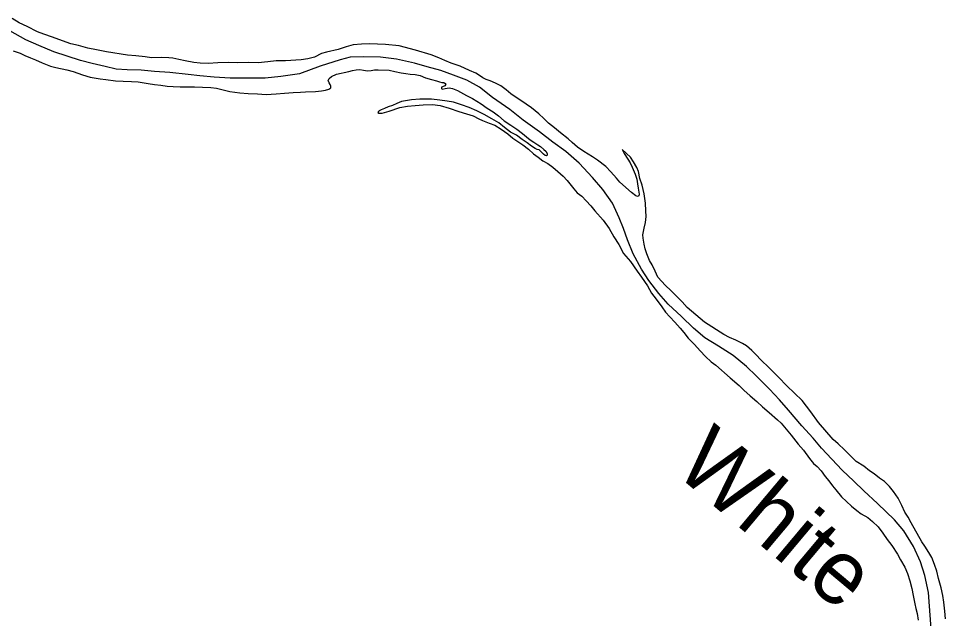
# Model space of a CAD drawing. Extents: x 1377389 to 1380723, y 1168351 to 1170484.
# Drawn here: x 1377867 to 1377943, y 1169789.7 to 1169838.9 of the extents above; entities that cross this region are included whole.
import ezdxf

# ---------------------------------------------------------------- set-up
doc = ezdxf.new("R2010")
doc.units = 0
doc.layers.add('B_Fill', color=7, linetype='Continuous')

msp = doc.modelspace()

# ---------------------------------------------------------------- linework, layer by layer
at = {"layer": 'B_Fill'}
for points in [[(1377901.437, 1169835.626), (1377900.799, 1169835.886), (1377899.515, 1169836.276), (1377898.184, 1169836.615), (1377897.069, 1169836.73), (1377896.408, 1169836.749), (1377895.786, 1169836.789), (1377895.087, 1169836.757), (1377894.408, 1169836.695), (1377893.852, 1169836.537), (1377893.169, 1169836.314), (1377892.225, 1169836.094), (1377891.828, 1169835.981), (1377891.246, 1169835.701), (1377890.7, 1169835.563), (1377890.142, 1169835.475), (1377888.874, 1169835.405), (1377888.103, 1169835.39), (1377887.415, 1169835.318), (1377886.627, 1169835.233), (1377885.815, 1169835.267), (1377884.966, 1169835.22), (1377884.194, 1169835.255), (1377883.305, 1169835.217), (1377882.515, 1169835.182), (1377881.854, 1169835.191), (1377881.352, 1169835.265), (1377880.637, 1169835.392), (1377880.113, 1169835.506), (1377879.62, 1169835.6), (1377879.298, 1169835.65), (1377878.687, 1169835.661), (1377877.877, 1169835.645), (1377877.354, 1169835.709), (1377876.591, 1169835.805), (1377875.918, 1169835.863), (1377874.198, 1169836.139), (1377873.363, 1169836.293), (1377872.647, 1169836.441), (1377871.901, 1169836.637), (1377871.265, 1169836.788), (1377870.577, 1169837.026), (1377869.757, 1169837.331), (1377869.048, 1169837.589), (1377868.522, 1169837.783), (1377867.688, 1169838.218), (1377867.038, 1169838.518), (1377866.457, 1169838.86)], [(1377901.437, 1169835.626), (1377900.799, 1169835.886), (1377899.515, 1169836.276), (1377898.184, 1169836.615), (1377897.069, 1169836.73), (1377896.408, 1169836.749), (1377895.786, 1169836.789), (1377895.087, 1169836.757), (1377894.408, 1169836.695), (1377893.852, 1169836.537), (1377893.169, 1169836.314), (1377892.225, 1169836.094), (1377891.828, 1169835.981), (1377891.246, 1169835.701), (1377890.7, 1169835.563), (1377890.142, 1169835.475), (1377888.874, 1169835.405), (1377888.103, 1169835.39), (1377887.415, 1169835.318), (1377886.627, 1169835.233), (1377885.815, 1169835.267), (1377884.966, 1169835.22), (1377884.194, 1169835.255), (1377883.305, 1169835.217), (1377882.515, 1169835.182), (1377881.854, 1169835.191), (1377881.352, 1169835.265), (1377880.637, 1169835.392), (1377880.113, 1169835.506), (1377879.62, 1169835.6), (1377879.298, 1169835.65), (1377878.687, 1169835.661), (1377877.877, 1169835.645), (1377877.354, 1169835.709), (1377876.591, 1169835.805), (1377875.918, 1169835.863), (1377874.198, 1169836.139), (1377873.363, 1169836.293), (1377872.647, 1169836.441), (1377871.901, 1169836.637), (1377871.265, 1169836.788), (1377870.577, 1169837.026), (1377869.757, 1169837.331), (1377869.048, 1169837.589), (1377868.522, 1169837.783), (1377867.688, 1169838.218), (1377867.038, 1169838.518), (1377866.457, 1169838.86)], [(1377919.466, 1169816.315), (1377918.653, 1169817.372), (1377918.053, 1169818.306), (1377917.383, 1169819.568), (1377916.917, 1169820.717), (1377916.567, 1169821.648), (1377916.229, 1169822.53), (1377915.671, 1169823.725), (1377914.886, 1169824.844), (1377914.044, 1169825.84), (1377912.947, 1169826.998), (1377911.846, 1169827.946), (1377910.791, 1169828.724), (1377909.704, 1169829.572), (1377908.353, 1169830.522), (1377907.255, 1169831.389), (1377905.832, 1169832.397), (1377904.785, 1169833.236), (1377903.736, 1169833.814), (1377902.653, 1169834.21), (1377901.6, 1169834.598), (1377900.469, 1169834.913), (1377899.449, 1169835.201), (1377897.957, 1169835.525), (1377896.651, 1169835.693), (1377895.259, 1169835.729), (1377894.169, 1169835.684), (1377893.335, 1169835.477), (1377891.71, 1169834.944), (1377890.008, 1169834.338), (1377888.484, 1169834.099), (1377887.187, 1169833.967), (1377885.786, 1169833.962), (1377884.315, 1169833.965), (1377883.021, 1169834.044), (1377881.836, 1169834.167), (1377880.872, 1169834.267), (1377879.366, 1169834.429), (1377878.132, 1169834.51), (1377877.038, 1169834.625), (1377875.876, 1169834.649), (1377874.984, 1169834.71), (1377874.076, 1169834.922), (1377873.018, 1169835.169), (1377872.049, 1169835.419), (1377869.865, 1169836.121), (1377868.647, 1169836.654), (1377867.582, 1169837.121), (1377866.248, 1169837.861)], [(1377866.519, 1169836.225), (1377867.096, 1169836.013), (1377867.502, 1169835.825), (1377867.959, 1169835.629), (1377868.354, 1169835.471), (1377868.922, 1169835.239), (1377869.591, 1169834.959), (1377870.026, 1169834.833), (1377870.942, 1169834.641), (1377871.457, 1169834.507), (1377872.206, 1169834.24), (1377872.853, 1169834.04), (1377873.657, 1169833.916), (1377874.129, 1169833.861), (1377874.913, 1169833.755), (1377875.555, 1169833.736), (1377876.226, 1169833.697), (1377876.778, 1169833.664), (1377877.592, 1169833.54), (1377878.116, 1169833.446), (1377878.648, 1169833.403), (1377879.15, 1169833.329), (1377879.662, 1169833.275), (1377880.214, 1169833.253), (1377880.884, 1169833.254), (1377881.395, 1169833.25), (1377882.056, 1169833.231), (1377882.747, 1169833.213), (1377883.2, 1169833.138), (1377884.309, 1169832.882)], [(1377866.519, 1169836.225), (1377867.096, 1169836.013), (1377867.502, 1169835.825), (1377867.959, 1169835.629), (1377868.354, 1169835.471), (1377868.922, 1169835.239), (1377869.591, 1169834.959), (1377870.026, 1169834.833), (1377870.942, 1169834.641), (1377871.457, 1169834.507), (1377872.206, 1169834.24), (1377872.853, 1169834.04), (1377873.657, 1169833.916), (1377874.129, 1169833.861), (1377874.913, 1169833.755), (1377875.555, 1169833.736), (1377876.226, 1169833.697), (1377876.778, 1169833.664), (1377877.592, 1169833.54), (1377878.116, 1169833.446), (1377878.648, 1169833.403), (1377879.15, 1169833.329), (1377879.662, 1169833.275), (1377880.214, 1169833.253), (1377880.884, 1169833.254), (1377881.395, 1169833.25), (1377882.056, 1169833.231), (1377882.747, 1169833.213), (1377883.2, 1169833.138), (1377884.309, 1169832.882)], [(1377937.974, 1169800.901), (1377937.585, 1169801.18), (1377937.124, 1169801.536), (1377936.756, 1169801.785), (1377936.284, 1169802.151), (1377935.671, 1169802.533), (1377935.217, 1169802.979), (1377934.701, 1169803.484), (1377934.194, 1169803.99), (1377933.763, 1169804.357), (1377932.568, 1169805.743), (1377931.941, 1169806.605), (1377931.231, 1169807.535), (1377929.982, 1169808.749), (1377929.28, 1169809.449), (1377928.535, 1169810.207), (1377927.854, 1169810.867), (1377927.46, 1169811.296), (1377927.099, 1169811.635), (1377926.677, 1169812.013), (1377926.34, 1169812.223), (1377925.792, 1169812.486), (1377925.274, 1169812.72), (1377924.796, 1169812.966), (1377923.223, 1169813.978), (1377922.523, 1169814.578), (1377921.804, 1169815.177), (1377921.38, 1169815.624), (1377920.904, 1169816.121), (1377920.481, 1169816.528), (1377920.005, 1169817.004), (1377919.716, 1169817.286), (1377919.405, 1169817.647), (1377919.169, 1169818.141), (1377918.933, 1169818.655), (1377918.701, 1169819.029), (1377918.484, 1169819.573), (1377918.361, 1169819.981), (1377918.269, 1169820.359), (1377918.194, 1169820.848), (1377918.175, 1169821.118), (1377918.268, 1169821.672), (1377918.373, 1169822.147), (1377918.428, 1169822.63), (1377918.414, 1169823.091), (1377918.374, 1169823.722), (1377918.28, 1169824.481), (1377918.108, 1169825.197), (1377917.93, 1169825.753), (1377917.802, 1169826.321), (1377917.661, 1169826.657), (1377917.407, 1169827.11), (1377917.155, 1169827.483), (1377916.465, 1169828.123), (1377916.645, 1169827.798), (1377916.93, 1169827.336), (1377917.13, 1169827.021), (1377917.301, 1169826.676), (1377917.529, 1169826.101), (1377917.672, 1169825.695), (1377917.734, 1169825.316), (1377917.785, 1169824.956), (1377917.835, 1169824.637), (1377917.86, 1169824.467), (1377917.824, 1169824.336), (1377917.736, 1169824.273), (1377917.605, 1169824.319), (1377917.246, 1169824.598), (1377916.268, 1169825.449), (1377916.007, 1169825.782), (1377915.551, 1169826.289), (1377915.137, 1169826.727), (1377914.46, 1169827.247), (1377914.041, 1169827.534), (1377913.337, 1169827.953), (1377912.815, 1169828.318), (1377912.364, 1169828.684), (1377912.044, 1169828.985), (1377911.408, 1169829.486), (1377910.935, 1169829.892), (1377910.442, 1169830.288), (1377910.05, 1169830.656), (1377909.628, 1169831.044), (1377909.032, 1169831.536), (1377908.612, 1169831.834), (1377908.152, 1169832.14), (1377907.702, 1169832.436), (1377907.354, 1169832.696), (1377906.954, 1169833.014), (1377906.523, 1169833.341), (1377906.086, 1169833.568), (1377905.64, 1169833.744), (1377905.326, 1169833.865), (1377905.051, 1169833.996), (1377904.785, 1169834.188), (1377904.469, 1169834.369), (1377903.962, 1169834.593), (1377903.18, 1169834.949), (1377902.451, 1169835.207), (1377901.924, 1169835.431), (1377901.437, 1169835.626)], [(1377937.974, 1169800.901), (1377937.585, 1169801.18), (1377937.124, 1169801.536), (1377936.756, 1169801.785), (1377936.284, 1169802.151), (1377935.671, 1169802.533), (1377935.217, 1169802.979), (1377934.701, 1169803.484), (1377934.194, 1169803.99), (1377933.763, 1169804.357), (1377932.568, 1169805.743), (1377931.941, 1169806.605), (1377931.231, 1169807.535), (1377929.982, 1169808.749), (1377929.28, 1169809.449), (1377928.535, 1169810.207), (1377927.854, 1169810.867), (1377927.46, 1169811.296), (1377927.099, 1169811.635), (1377926.677, 1169812.013), (1377926.34, 1169812.223), (1377925.792, 1169812.486), (1377925.274, 1169812.72), (1377924.796, 1169812.966), (1377923.223, 1169813.978), (1377922.523, 1169814.578), (1377921.804, 1169815.177), (1377921.38, 1169815.624), (1377920.904, 1169816.121), (1377920.481, 1169816.528), (1377920.005, 1169817.004), (1377919.716, 1169817.286), (1377919.405, 1169817.647), (1377919.169, 1169818.141), (1377918.933, 1169818.655), (1377918.701, 1169819.029), (1377918.484, 1169819.573), (1377918.361, 1169819.981), (1377918.269, 1169820.359), (1377918.194, 1169820.848), (1377918.175, 1169821.118), (1377918.268, 1169821.672), (1377918.373, 1169822.147), (1377918.428, 1169822.63), (1377918.414, 1169823.091), (1377918.374, 1169823.722), (1377918.28, 1169824.481), (1377918.108, 1169825.197), (1377917.93, 1169825.753), (1377917.802, 1169826.321), (1377917.661, 1169826.657), (1377917.407, 1169827.11), (1377917.155, 1169827.483), (1377916.465, 1169828.123), (1377916.645, 1169827.798), (1377916.93, 1169827.336), (1377917.13, 1169827.021), (1377917.301, 1169826.676), (1377917.529, 1169826.101), (1377917.672, 1169825.695), (1377917.734, 1169825.316), (1377917.785, 1169824.956), (1377917.835, 1169824.637), (1377917.86, 1169824.467), (1377917.824, 1169824.336), (1377917.736, 1169824.273), (1377917.605, 1169824.319), (1377917.246, 1169824.598), (1377916.268, 1169825.449), (1377916.007, 1169825.782), (1377915.551, 1169826.289), (1377915.137, 1169826.727), (1377914.46, 1169827.247), (1377914.041, 1169827.534), (1377913.337, 1169827.953), (1377912.815, 1169828.318), (1377912.364, 1169828.684), (1377912.044, 1169828.985), (1377911.408, 1169829.486), (1377910.935, 1169829.892), (1377910.442, 1169830.288), (1377910.05, 1169830.656), (1377909.628, 1169831.044), (1377909.032, 1169831.536), (1377908.612, 1169831.834), (1377908.152, 1169832.14), (1377907.702, 1169832.436), (1377907.354, 1169832.696), (1377906.954, 1169833.014), (1377906.523, 1169833.341), (1377906.086, 1169833.568), (1377905.64, 1169833.744), (1377905.326, 1169833.865), (1377905.051, 1169833.996), (1377904.785, 1169834.188), (1377904.469, 1169834.369), (1377903.962, 1169834.593), (1377903.18, 1169834.949), (1377902.451, 1169835.207), (1377901.924, 1169835.431), (1377901.437, 1169835.626)], [(1377884.309, 1169832.882), (1377885.113, 1169832.757), (1377885.815, 1169832.72), (1377886.577, 1169832.674), (1377887.279, 1169832.626), (1377888.098, 1169832.682), (1377888.786, 1169832.754), (1377889.485, 1169832.807), (1377890.085, 1169832.836), (1377890.505, 1169832.85), (1377891.315, 1169832.865), (1377891.803, 1169832.931), (1377892.152, 1169832.992), (1377892.41, 1169833.061), (1377892.586, 1169833.177), (1377892.582, 1169833.327), (1377892.528, 1169833.456), (1377892.454, 1169833.584), (1377892.367, 1169833.782), (1377892.452, 1169833.945), (1377892.648, 1169834.101), (1377893.042, 1169834.294), (1377894.055, 1169834.527), (1377894.363, 1169834.597), (1377894.672, 1169834.657), (1377894.951, 1169834.686), (1377895.263, 1169834.626), (1377895.595, 1169834.577), (1377895.875, 1169834.596), (1377896.153, 1169834.665), (1377896.473, 1169834.665), (1377897.355, 1169834.623), (1377897.829, 1169834.508), (1377898.353, 1169834.404), (1377898.725, 1169834.356), (1377899.087, 1169834.297), (1377899.488, 1169834.28), (1377899.901, 1169834.183), (1377900.347, 1169834.006), (1377900.832, 1169833.861), (1377901.246, 1169833.744), (1377901.488, 1169833.672), (1377901.69, 1169833.628), (1377901.851, 1169833.603), (1377901.963, 1169833.547), (1377902.006, 1169833.448), (1377901.929, 1169833.355), (1377901.731, 1169833.268), (1377901.653, 1169833.226), (1377901.646, 1169833.125), (1377901.708, 1169833.067), (1377901.946, 1169833.115), (1377902.295, 1169833.176), (1377902.556, 1169833.134), (1377902.962, 1169832.967), (1377903.696, 1169832.539), (1377904.193, 1169832.314), (1377904.918, 1169831.866), (1377905.399, 1169831.52), (1377905.889, 1169831.215), (1377906.32, 1169830.878), (1377906.803, 1169830.482), (1377907.334, 1169830.128), (1377907.825, 1169829.793), (1377908.297, 1169829.437), (1377908.615, 1169829.166), (1377908.923, 1169828.925), (1377909.22, 1169828.714), (1377909.557, 1169828.504), (1377909.772, 1169828.361), (1377910.059, 1169828.129), (1377910.204, 1169827.983), (1377910.31, 1169827.786), (1377910.324, 1169827.646), (1377910.276, 1169827.605), (1377910.165, 1169827.631), (1377910.021, 1169827.737), (1377909.928, 1169827.834), (1377909.815, 1169827.941), (1377909.67, 1169828.097), (1377909.488, 1169828.131), (1377909.326, 1169828.196), (1377909.029, 1169828.407), (1377908.691, 1169828.667), (1377908.262, 1169828.944), (1377907.811, 1169829.291), (1377907.302, 1169829.555), (1377906.83, 1169829.921), (1377906.348, 1169830.297), (1377905.787, 1169830.65), (1377905.165, 1169830.991), (1377904.545, 1169831.303), (1377903.916, 1169831.563), (1377903.309, 1169831.784), (1377902.642, 1169831.994), (1377902.119, 1169832.087), (1377901.525, 1169832.179), (1377900.832, 1169832.247), (1377899.882, 1169832.237), (1377899.193, 1169832.194), (1377898.386, 1169832.068)], [(1377884.309, 1169832.882), (1377885.113, 1169832.757), (1377885.815, 1169832.72), (1377886.577, 1169832.674), (1377887.279, 1169832.626), (1377888.098, 1169832.682), (1377888.786, 1169832.754), (1377889.485, 1169832.807), (1377890.085, 1169832.836), (1377890.505, 1169832.85), (1377891.315, 1169832.865), (1377891.803, 1169832.931), (1377892.152, 1169832.992), (1377892.41, 1169833.061), (1377892.586, 1169833.177), (1377892.582, 1169833.327), (1377892.528, 1169833.456), (1377892.454, 1169833.584), (1377892.367, 1169833.782), (1377892.452, 1169833.945), (1377892.648, 1169834.101), (1377893.042, 1169834.294), (1377894.055, 1169834.527), (1377894.363, 1169834.597), (1377894.672, 1169834.657), (1377894.951, 1169834.686), (1377895.263, 1169834.626), (1377895.595, 1169834.577), (1377895.875, 1169834.596), (1377896.153, 1169834.665), (1377896.473, 1169834.665), (1377897.355, 1169834.623), (1377897.829, 1169834.508), (1377898.353, 1169834.404), (1377898.725, 1169834.356), (1377899.087, 1169834.297), (1377899.488, 1169834.28), (1377899.901, 1169834.183), (1377900.347, 1169834.006), (1377900.832, 1169833.861), (1377901.246, 1169833.744), (1377901.488, 1169833.672), (1377901.69, 1169833.628), (1377901.851, 1169833.603), (1377901.963, 1169833.547), (1377902.006, 1169833.448), (1377901.929, 1169833.355), (1377901.731, 1169833.268), (1377901.653, 1169833.226), (1377901.646, 1169833.125), (1377901.708, 1169833.067), (1377901.946, 1169833.115), (1377902.295, 1169833.176), (1377902.556, 1169833.134), (1377902.962, 1169832.967), (1377903.696, 1169832.539), (1377904.193, 1169832.314), (1377904.918, 1169831.866), (1377905.399, 1169831.52), (1377905.889, 1169831.215), (1377906.32, 1169830.878), (1377906.803, 1169830.482), (1377907.334, 1169830.128), (1377907.825, 1169829.793), (1377908.297, 1169829.437), (1377908.615, 1169829.166), (1377908.923, 1169828.925), (1377909.22, 1169828.714), (1377909.557, 1169828.504), (1377909.772, 1169828.361), (1377910.059, 1169828.129), (1377910.204, 1169827.983), (1377910.31, 1169827.786), (1377910.324, 1169827.646), (1377910.276, 1169827.605), (1377910.165, 1169827.631), (1377910.021, 1169827.737), (1377909.928, 1169827.834), (1377909.815, 1169827.941), (1377909.67, 1169828.097), (1377909.488, 1169828.131), (1377909.326, 1169828.196), (1377909.029, 1169828.407), (1377908.691, 1169828.667), (1377908.262, 1169828.944), (1377907.811, 1169829.291), (1377907.302, 1169829.555), (1377906.83, 1169829.921), (1377906.348, 1169830.297), (1377905.787, 1169830.65), (1377905.165, 1169830.991), (1377904.545, 1169831.303), (1377903.916, 1169831.563), (1377903.309, 1169831.784), (1377902.642, 1169831.994), (1377902.119, 1169832.087), (1377901.525, 1169832.179), (1377900.832, 1169832.247), (1377899.882, 1169832.237), (1377899.193, 1169832.194), (1377898.386, 1169832.068)], [(1377898.386, 1169832.068), (1377897.991, 1169831.895), (1377897.646, 1169831.734), (1377897.279, 1169831.612), (1377896.973, 1169831.472), (1377896.707, 1169831.363), (1377896.549, 1169831.288), (1377896.481, 1169831.225), (1377896.443, 1169831.144), (1377896.515, 1169831.096), (1377896.785, 1169831.105), (1377897.36, 1169831.273), (1377898.252, 1169831.553), (1377898.869, 1169831.663), (1377899.497, 1169831.733), (1377900.156, 1169831.794), (1377900.906, 1169831.808), (1377901.539, 1169831.728), (1377902.287, 1169831.501), (1377903.076, 1169831.246), (1377903.712, 1169831.055), (1377904.258, 1169830.882), (1377904.706, 1169830.636), (1377905.02, 1169830.505), (1377905.568, 1169830.282), (1377906.034, 1169830.107), (1377906.554, 1169829.782), (1377907.097, 1169829.408), (1377907.498, 1169829.06), (1377907.835, 1169828.84), (1377908.316, 1169828.495), (1377908.778, 1169828.138), (1377909.21, 1169827.771), (1377909.578, 1169827.502), (1377909.958, 1169827.203), (1377910.366, 1169826.966), (1377910.785, 1169826.668), (1377911.187, 1169826.31), (1377911.629, 1169825.933), (1377911.971, 1169825.573), (1377912.502, 1169824.888), (1377912.792, 1169824.576), (1377913.151, 1169824.297), (1377913.524, 1169823.908), (1377913.907, 1169823.499), (1377914.24, 1169823.098), (1377914.905, 1169822.327), (1377915.406, 1169821.651), (1377915.778, 1169820.971), (1377916.208, 1169820.323), (1377916.591, 1169819.603), (1377917.142, 1169818.949), (1377917.688, 1169818.134), (1377918.053, 1169817.664), (1377918.556, 1169816.948), (1377918.865, 1169816.346), (1377919.271, 1169815.838), (1377919.711, 1169815.23), (1377920.015, 1169814.778), (1377920.377, 1169814.409), (1377920.791, 1169813.961), (1377921.217, 1169813.483), (1377921.538, 1169813.112), (1377921.893, 1169812.662), (1377922.41, 1169812.127), (1377922.866, 1169811.61), (1377923.301, 1169811.163), (1377923.765, 1169810.716), (1377924.164, 1169810.438), (1377925.328, 1169809.402), (1377926.058, 1169808.764), (1377926.46, 1169808.396), (1377926.955, 1169807.93), (1377927.5, 1169807.456), (1377927.974, 1169807.02), (1377928.529, 1169806.556), (1377929.198, 1169805.966), (1377929.508, 1169805.675), (1377929.913, 1169805.197), (1377930.329, 1169804.698), (1377930.893, 1169803.954), (1377931.329, 1169803.457), (1377931.83, 1169802.791), (1377932.163, 1169802.38), (1377932.461, 1169802.129), (1377932.782, 1169801.788), (1377933.128, 1169801.298), (1377933.408, 1169800.966), (1377933.721, 1169800.555), (1377933.982, 1169800.212), (1377934.451, 1169799.635), (1377934.853, 1169799.267), (1377935.275, 1169798.88), (1377935.717, 1169798.523), (1377936.075, 1169798.253), (1377936.605, 1169797.959), (1377937.006, 1169797.621), (1377937.45, 1169797.184), (1377937.836, 1169796.675), (1377938.203, 1169796.145), (1377938.589, 1169795.646)], [(1377898.386, 1169832.068), (1377897.991, 1169831.895), (1377897.646, 1169831.734), (1377897.279, 1169831.612), (1377896.973, 1169831.472), (1377896.707, 1169831.363), (1377896.549, 1169831.288), (1377896.481, 1169831.225), (1377896.443, 1169831.144), (1377896.515, 1169831.096), (1377896.785, 1169831.105), (1377897.36, 1169831.273), (1377898.252, 1169831.553), (1377898.869, 1169831.663), (1377899.497, 1169831.733), (1377900.156, 1169831.794), (1377900.906, 1169831.808), (1377901.539, 1169831.728), (1377902.287, 1169831.501), (1377903.076, 1169831.246), (1377903.712, 1169831.055), (1377904.258, 1169830.882), (1377904.706, 1169830.636), (1377905.02, 1169830.505), (1377905.568, 1169830.282), (1377906.034, 1169830.107), (1377906.554, 1169829.782), (1377907.097, 1169829.408), (1377907.498, 1169829.06), (1377907.835, 1169828.84), (1377908.316, 1169828.495), (1377908.778, 1169828.138), (1377909.21, 1169827.771), (1377909.578, 1169827.502), (1377909.958, 1169827.203), (1377910.366, 1169826.966), (1377910.785, 1169826.668), (1377911.187, 1169826.31), (1377911.629, 1169825.933), (1377911.971, 1169825.573), (1377912.502, 1169824.888), (1377912.792, 1169824.576), (1377913.151, 1169824.297), (1377913.524, 1169823.908), (1377913.907, 1169823.499), (1377914.24, 1169823.098), (1377914.905, 1169822.327), (1377915.406, 1169821.651), (1377915.778, 1169820.971), (1377916.208, 1169820.323), (1377916.591, 1169819.603), (1377917.142, 1169818.949), (1377917.688, 1169818.134), (1377918.053, 1169817.664), (1377918.556, 1169816.948), (1377918.865, 1169816.346), (1377919.271, 1169815.838), (1377919.711, 1169815.23), (1377920.015, 1169814.778), (1377920.377, 1169814.409), (1377920.791, 1169813.961), (1377921.217, 1169813.483), (1377921.538, 1169813.112), (1377921.893, 1169812.662), (1377922.41, 1169812.127), (1377922.866, 1169811.61), (1377923.301, 1169811.163), (1377923.765, 1169810.716), (1377924.164, 1169810.438), (1377925.328, 1169809.402), (1377926.058, 1169808.764), (1377926.46, 1169808.396), (1377926.955, 1169807.93), (1377927.5, 1169807.456), (1377927.974, 1169807.02), (1377928.529, 1169806.556), (1377929.198, 1169805.966), (1377929.508, 1169805.675), (1377929.913, 1169805.197), (1377930.329, 1169804.698), (1377930.893, 1169803.954), (1377931.329, 1169803.457), (1377931.83, 1169802.791), (1377932.163, 1169802.38), (1377932.461, 1169802.129), (1377932.782, 1169801.788), (1377933.128, 1169801.298), (1377933.408, 1169800.966), (1377933.721, 1169800.555), (1377933.982, 1169800.212), (1377934.451, 1169799.635), (1377934.853, 1169799.267), (1377935.275, 1169798.88), (1377935.717, 1169798.523), (1377936.075, 1169798.253), (1377936.605, 1169797.959), (1377937.006, 1169797.621), (1377937.45, 1169797.184), (1377937.836, 1169796.675), (1377938.203, 1169796.145), (1377938.589, 1169795.646)], [(1377941.806, 1169788.809), (1377941.602, 1169791.791), (1377941.278, 1169793.195), (1377940.942, 1169794.327), (1377940.353, 1169795.582), (1377939.562, 1169796.86), (1377938.813, 1169797.749), (1377937.42, 1169799.088), (1377936.296, 1169800.146), (1377935.461, 1169800.931), (1377934.502, 1169801.843), (1377933.674, 1169802.719), (1377932.805, 1169803.624), (1377932.128, 1169804.445), (1377931.216, 1169805.469), (1377930.115, 1169806.747), (1377929.377, 1169807.606), (1377928.559, 1169808.483), (1377927.465, 1169809.551), (1377926.67, 1169810.328), (1377925.56, 1169811.235), (1377924.366, 1169811.999), (1377923.263, 1169812.686), (1377922.318, 1169813.468), (1377921.347, 1169814.43), (1377920.244, 1169815.448), (1377919.466, 1169816.315)], [(1377942.981, 1169789.629), (1377942.921, 1169790.259), (1377942.837, 1169791.018), (1377942.771, 1169791.548), (1377942.631, 1169792.185), (1377942.407, 1169792.95), (1377942.268, 1169793.537), (1377942.081, 1169794.083), (1377941.862, 1169794.667), (1377941.629, 1169795.091), (1377941.303, 1169795.592), (1377941.041, 1169795.965), (1377940.172, 1169797.502), (1377939.917, 1169797.975), (1377939.654, 1169798.398), (1377939.397, 1169798.921), (1377939.098, 1169799.533), (1377938.72, 1169800.093), (1377938.388, 1169800.483), (1377937.974, 1169800.901)], [(1377942.981, 1169789.629), (1377942.921, 1169790.259), (1377942.837, 1169791.018), (1377942.771, 1169791.548), (1377942.631, 1169792.185), (1377942.407, 1169792.95), (1377942.268, 1169793.537), (1377942.081, 1169794.083), (1377941.862, 1169794.667), (1377941.629, 1169795.091), (1377941.303, 1169795.592), (1377941.041, 1169795.965), (1377940.172, 1169797.502), (1377939.917, 1169797.975), (1377939.654, 1169798.398), (1377939.397, 1169798.921), (1377939.098, 1169799.533), (1377938.72, 1169800.093), (1377938.388, 1169800.483), (1377937.974, 1169800.901)], [(1377938.589, 1169795.646), (1377939.052, 1169794.939), (1377939.306, 1169794.475), (1377939.646, 1169793.865), (1377939.861, 1169793.37), (1377940.051, 1169792.754), (1377940.231, 1169792.118), (1377940.338, 1169791.56), (1377940.48, 1169790.863), (1377940.552, 1169790.494), (1377940.655, 1169790.066), (1377940.752, 1169789.527)], [(1377938.589, 1169795.646), (1377939.052, 1169794.939), (1377939.306, 1169794.475), (1377939.646, 1169793.865), (1377939.861, 1169793.37), (1377940.051, 1169792.754), (1377940.231, 1169792.118), (1377940.338, 1169791.56), (1377940.48, 1169790.863), (1377940.552, 1169790.494), (1377940.655, 1169790.066), (1377940.752, 1169789.527)]]:
    msp.add_lwpolyline(points, dxfattribs=at)

# ---------------------------------------------------------------- texts
msp.add_text('White', height=5.28, rotation=320, dxfattribs=at).set_placement((1377920.583, 1169801.732))

doc.saveas('drawing.dxf')
